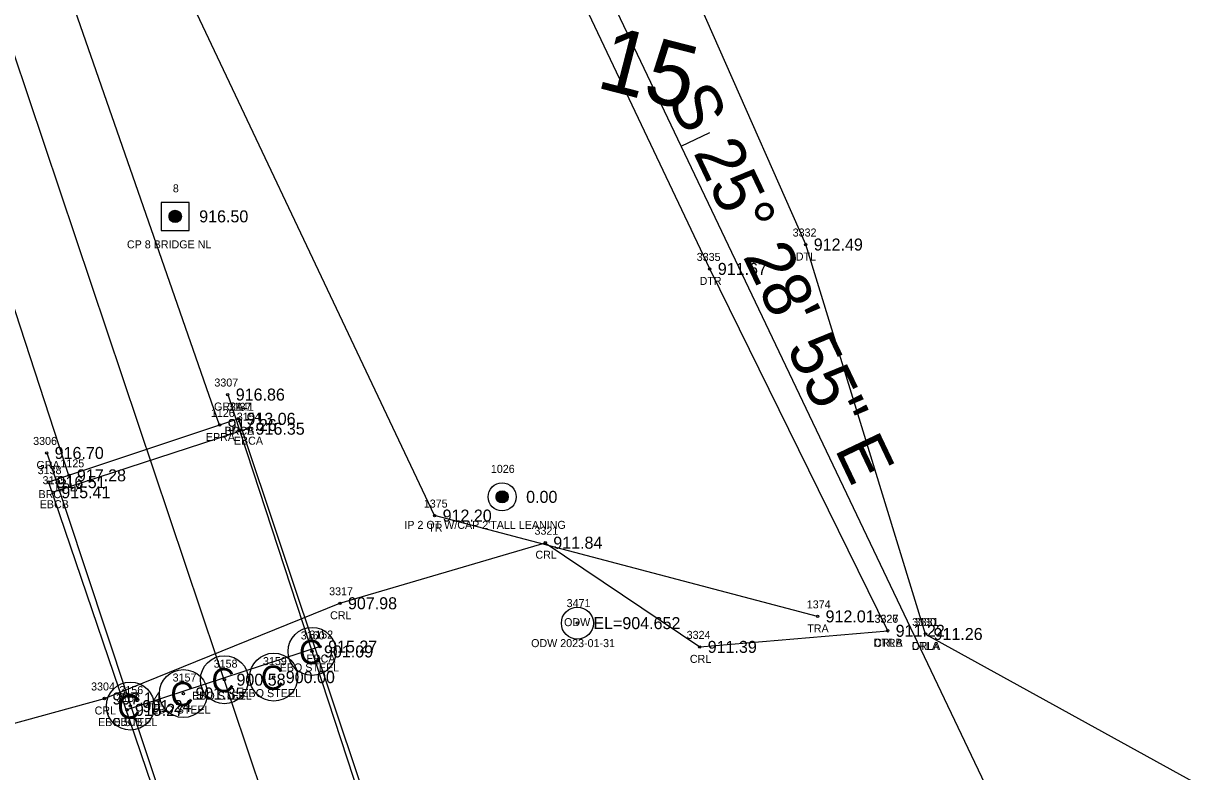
# Model space of a CAD drawing. Extents: x 1528109 to 1531398, y 1157799 to 1162548.
# Drawn here: x 1529613.7 to 1529759.7, y 1160294.1 to 1160387.6 of the extents above; entities that cross this region are included whole.
import ezdxf

# ---------------------------------------------------------------- set-up
doc = ezdxf.new("R2010")
doc.units = 0
for name, color, linetype in [('RD_EX_Bridge', 7, 'Continuous'), ('RD_EX_Bridge_txCode', 7, 'Continuous'), ('RD_EX_DV_Prop_txCode', 7, 'Continuous'), ('RD_EX_DV_PropPin', 7, 'Continuous'), ('RD_EX_GuardRail', 7, 'Continuous'), ('RD_EX_GuardRail_txCode', 7, 'Continuous'), ('RD_EX_H2O', 7, 'Continuous'), ('RD_EX_H2O_txCode', 7, 'Continuous'), ('RD_EX_Road', 7, 'Continuous'), ('RD_EX_Road_txCode', 7, 'Continuous'), ('RD_EX_TX_Bridge_ELEV', 7, 'Continuous'), ('RD_EX_TX_DV_Prop_ELEV', 7, 'Continuous'), ('RD_EX_TX_GuardRail_ELEV', 7, 'Continuous'), ('RD_EX_TX_H2O_ELEV', 7, 'Continuous'), ('RD_EX_TX_Road_ELEV', 7, 'Continuous'), ('RD_EX_TX_VEG_ELEV', 7, 'Continuous'), ('RD_EX_VEG', 7, 'Continuous'), ('RD_EX_VEG_txCode', 7, 'Continuous'), ('RD_HC_Cl', 7, 'Continuous'), ('RD_HC_Data', 7, 'Continuous'), ('RD_HC_Data_Tic', 7, 'Continuous'), ('RD_HC_Survey', 7, 'Continuous'), ('RD_HC_Survey_ELEV', 7, 'Continuous'), ('RD_HC_Survey_txCode', 7, 'Continuous'), ('RD_HC_TX_Sta50', 7, 'Continuous'), ('RD_SMD_Locator', 7, 'Continuous')]:
    doc.layers.add(name, color=color, linetype=linetype)

msp = doc.modelspace()

# ---------------------------------------------------------------- linework, layer by layer
at = {"layer": 'RD_EX_Bridge'}
for p, q in [((1529641.69, 1160336.95), (1529617.41, 1160329.01)), ((1529650.75, 1160309.72), (1529626.61, 1160301.81))]:
    msp.add_line(p, q, dxfattribs=at)
msp.add_lwpolyline([(1529640.55, 1160338.19), (1529616.81, 1160330.27), (1529655.43, 1160216.77), (1529678.49, 1160224.61), (1529640.55, 1160338.19)], dxfattribs=at)
for centre in [(1529649.74, 1160309.11), (1529638.8, 1160305.58), (1529644.96, 1160305.9), (1529633.67, 1160303.85), (1529627.04, 1160302.28)]:
    msp.add_circle(centre, 3, dxfattribs=at)
at = {"layer": 'RD_EX_DV_PropPin'}
for p, q in [((1529672.77, 1160328.23), (1529672.77, 1160328.62)), ((1529672.8, 1160328.13), (1529672.8, 1160328.73)), ((1529672.84, 1160328.06), (1529672.84, 1160328.8)), ((1529672.87, 1160328), (1529672.87, 1160328.85)), ((1529672.91, 1160327.95), (1529672.91, 1160328.9)), ((1529672.94, 1160327.91), (1529672.94, 1160328.94)), ((1529672.98, 1160327.88), (1529672.98, 1160328.98)), ((1529673.01, 1160327.85), (1529673.01, 1160329.01)), ((1529673.05, 1160327.82), (1529673.05, 1160329.04)), ((1529673.08, 1160327.79), (1529673.08, 1160329.06)), ((1529673.12, 1160327.77), (1529673.12, 1160329.08)), ((1529673.15, 1160327.75), (1529673.15, 1160329.1)), ((1529673.19, 1160327.74), (1529673.19, 1160329.12)), ((1529673.22, 1160327.72), (1529673.22, 1160329.14)), ((1529673.26, 1160327.71), (1529673.26, 1160329.15)), ((1529673.29, 1160327.7), (1529673.29, 1160329.16)), ((1529673.33, 1160327.69), (1529673.33, 1160329.17)), ((1529673.36, 1160327.68), (1529673.36, 1160329.18)), ((1529673.4, 1160327.67), (1529673.4, 1160329.18)), ((1529673.43, 1160327.67), (1529673.43, 1160329.19)), ((1529673.47, 1160327.67), (1529673.47, 1160329.19)), ((1529673.5, 1160327.67), (1529673.5, 1160329.19)), ((1529673.54, 1160327.67), (1529673.54, 1160329.19)), ((1529673.57, 1160327.67), (1529673.57, 1160329.19)), ((1529673.61, 1160327.67), (1529673.61, 1160329.18)), ((1529673.64, 1160327.68), (1529673.64, 1160329.18)), ((1529673.68, 1160327.69), (1529673.68, 1160329.17)), ((1529673.71, 1160327.7), (1529673.71, 1160329.16)), ((1529673.75, 1160327.71), (1529673.75, 1160329.15)), ((1529673.78, 1160327.72), (1529673.78, 1160329.14)), ((1529673.82, 1160327.74), (1529673.82, 1160329.12)), ((1529673.85, 1160327.75), (1529673.85, 1160329.1)), ((1529673.89, 1160327.77), (1529673.89, 1160329.08)), ((1529673.92, 1160327.79), (1529673.92, 1160329.06)), ((1529673.96, 1160327.82), (1529673.96, 1160329.04)), ((1529673.99, 1160327.85), (1529673.99, 1160329.01)), ((1529674.03, 1160327.88), (1529674.03, 1160328.98)), ((1529674.06, 1160327.91), (1529674.06, 1160328.94)), ((1529674.1, 1160327.95), (1529674.1, 1160328.9)), ((1529674.13, 1160328), (1529674.13, 1160328.85)), ((1529674.17, 1160328.06), (1529674.17, 1160328.8)), ((1529674.2, 1160328.13), (1529674.2, 1160328.73)), ((1529674.24, 1160328.23), (1529674.24, 1160328.62))]:
    msp.add_line(p, q, dxfattribs=at)
for radius in [1.75, 0.761]:
    msp.add_circle((1529673.5, 1160328.43), radius, dxfattribs=at)
at = {"layer": 'RD_EX_GuardRail'}
for points in [[(1529639.21, 1160341.22), (1529658.79, 1160281.43), (1529679.51, 1160220.29)], [(1529616.58, 1160333.92), (1529636.5, 1160273.84), (1529656.54, 1160212.79)]]:
    msp.add_lwpolyline(points, dxfattribs=at)
at = {"layer": 'RD_EX_H2O'}
for points in [[(1529721.68, 1160311.69), (1529699.45, 1160356.92), (1529667.22, 1160424.93), (1529635.88, 1160475.03)], [(1529212.56, 1160420.69), (1529289.94, 1160452.31), (1529331.04, 1160457.54), (1529371.94, 1160452.7), (1529411.5, 1160420.02), (1529456.02, 1160392.77), (1529494.52, 1160341.06), (1529560.21, 1160297.91), (1529595.85, 1160295.56), (1529623.8, 1160303.23), (1529653.23, 1160315.13), (1529678.89, 1160322.7), (1529698.19, 1160309.68), (1529721.68, 1160311.69)], [(1529726.41, 1160311.29), (1529711.44, 1160359.97), (1529679.1, 1160433.25), (1529696.96, 1160440.59)], [(1529726.41, 1160311.29), (1529822.85, 1160258.09), (1529888.47, 1160243.37), (1529986.9, 1160229.42), (1530037.08, 1160228.61), (1530104.23, 1160168.21), (1530147.93, 1160110.54), (1530175.68, 1160088.08)]]:
    msp.add_lwpolyline(points, dxfattribs=at)
for radius in [2, 0.15]:
    msp.add_circle((1529682.9, 1160312.65), radius, dxfattribs=at)
at = {"layer": 'RD_EX_Road'}
for points in [[(1529638.19, 1160337.41), (1529618.52, 1160393.92), (1529601.47, 1160445.09), (1529582.35, 1160502.18), (1529566.78, 1160548.91), (1529548.34, 1160605.67), (1529547.84, 1160613.14)], [(1529619.36, 1160331.12), (1529600.6, 1160388.5), (1529583.59, 1160439.6), (1529564.67, 1160495.86), (1529548.92, 1160543.15), (1529530.19, 1160599.08), (1529525.69, 1160605.63)]]:
    msp.add_lwpolyline(points, dxfattribs=at)
at = {"layer": 'RD_EX_VEG'}
msp.add_lwpolyline([(1529712.92, 1160313.49), (1529665.06, 1160326.09), (1529626.42, 1160407.72), (1529580.03, 1160531.48), (1529510.74, 1160760.21), (1529455.97, 1160902.21), (1529420.7, 1161006.64), (1529376.36, 1161143.49), (1529336.53, 1161275.85), (1529306.04, 1161391.66)], dxfattribs=at)
at = {"layer": 'RD_HC_Cl'}
for p, q in [((1529913.5, 1159487.74), (1529527.85, 1160635.77)), ((1529658.39, 1160450.88), (1529753.92, 1160250.44))]:
    msp.add_line(p, q, dxfattribs=at)
at = {"layer": 'RD_HC_Data_Tic'}
msp.add_line((1529695.86, 1160372.26), (1529699.47, 1160373.98), dxfattribs=at)
at = {"layer": 'RD_HC_Survey'}
for p, q in [((1529631.89, 1160363.31), (1529631.89, 1160363.67)), ((1529631.91, 1160363.23), (1529631.91, 1160363.75)), ((1529631.94, 1160363.17), (1529631.94, 1160363.81)), ((1529631.96, 1160363.12), (1529631.96, 1160363.86)), ((1529631.99, 1160363.08), (1529631.99, 1160363.9)), ((1529632.01, 1160363.04), (1529632.01, 1160363.94)), ((1529632.04, 1160363.01), (1529632.04, 1160363.97)), ((1529632.06, 1160362.98), (1529632.06, 1160364)), ((1529632.09, 1160362.95), (1529632.09, 1160364.03)), ((1529632.11, 1160362.93), (1529632.11, 1160364.05)), ((1529632.13, 1160362.9), (1529632.13, 1160364.07)), ((1529632.16, 1160362.88), (1529632.16, 1160364.09)), ((1529632.18, 1160362.87), (1529632.18, 1160364.11)), ((1529632.21, 1160362.85), (1529632.21, 1160364.13)), ((1529632.23, 1160362.83), (1529632.23, 1160364.14)), ((1529632.26, 1160362.82), (1529632.26, 1160364.16)), ((1529632.28, 1160362.8), (1529632.28, 1160364.17)), ((1529632.31, 1160362.79), (1529632.31, 1160364.18)), ((1529632.33, 1160362.78), (1529632.33, 1160364.2)), ((1529632.36, 1160362.77), (1529632.36, 1160364.21)), ((1529632.38, 1160362.76), (1529632.38, 1160364.21)), ((1529632.41, 1160362.75), (1529632.41, 1160364.22)), ((1529632.43, 1160362.75), (1529632.43, 1160364.23)), ((1529632.46, 1160362.74), (1529632.46, 1160364.24)), ((1529632.48, 1160362.73), (1529632.48, 1160364.24)), ((1529632.51, 1160362.73), (1529632.51, 1160364.25)), ((1529632.53, 1160362.73), (1529632.53, 1160364.25)), ((1529632.56, 1160362.72), (1529632.56, 1160364.25)), ((1529632.58, 1160362.72), (1529632.58, 1160364.26)), ((1529632.61, 1160362.72), (1529632.61, 1160364.26)), ((1529632.63, 1160362.72), (1529632.63, 1160364.26)), ((1529632.65, 1160362.72), (1529632.65, 1160364.26)), ((1529632.68, 1160362.72), (1529632.68, 1160364.26)), ((1529632.7, 1160362.72), (1529632.7, 1160364.25)), ((1529632.73, 1160362.72), (1529632.73, 1160364.25)), ((1529632.75, 1160362.73), (1529632.75, 1160364.25)), ((1529632.78, 1160362.73), (1529632.78, 1160364.24)), ((1529632.8, 1160362.74), (1529632.8, 1160364.24)), ((1529632.83, 1160362.74), (1529632.83, 1160364.23)), ((1529632.85, 1160362.75), (1529632.85, 1160364.23)), ((1529632.88, 1160362.76), (1529632.88, 1160364.22)), ((1529632.9, 1160362.77), (1529632.9, 1160364.21)), ((1529632.93, 1160362.78), (1529632.93, 1160364.2)), ((1529632.95, 1160362.79), (1529632.95, 1160364.19)), ((1529632.98, 1160362.8), (1529632.98, 1160364.18)), ((1529633, 1160362.81), (1529633, 1160364.17)), ((1529633.03, 1160362.83), (1529633.03, 1160364.15)), ((1529633.05, 1160362.84), (1529633.05, 1160364.14)), ((1529633.08, 1160362.86), (1529633.08, 1160364.12)), ((1529633.1, 1160362.87), (1529633.1, 1160364.1)), ((1529633.12, 1160362.89), (1529633.12, 1160364.08)), ((1529633.15, 1160362.92), (1529633.15, 1160364.06)), ((1529633.17, 1160362.94), (1529633.17, 1160364.04)), ((1529633.2, 1160362.96), (1529633.2, 1160364.01)), ((1529633.22, 1160362.99), (1529633.22, 1160363.98)), ((1529633.25, 1160363.02), (1529633.25, 1160363.95)), ((1529633.27, 1160363.06), (1529633.27, 1160363.92)), ((1529633.3, 1160363.1), (1529633.3, 1160363.88)), ((1529633.32, 1160363.14), (1529633.32, 1160363.83)), ((1529633.35, 1160363.2), (1529633.35, 1160363.78)), ((1529633.37, 1160363.27), (1529633.37, 1160363.71)), ((1529633.4, 1160363.38), (1529633.4, 1160363.6))]:
    msp.add_line(p, q, dxfattribs=at)
msp.add_lwpolyline([(1529634.39, 1160365.24), (1529630.89, 1160365.24), (1529630.89, 1160361.74), (1529634.39, 1160361.74)], close=True, dxfattribs=at)
msp.add_circle((1529632.64, 1160363.49), 0.769, dxfattribs=at)
at = {"layer": 'RD_SMD_Locator'}
for centre in [(1529632.64, 1160363.49), (1529711.44, 1160359.97), (1529699.45, 1160356.92), (1529639.21, 1160341.22), (1529640.55, 1160338.19), (1529640.55, 1160338.19), (1529638.19, 1160337.41), (1529641.69, 1160336.95), (1529616.58, 1160333.92), (1529619.36, 1160331.12), (1529616.81, 1160330.27), (1529617.41, 1160329.01), (1529673.5, 1160328.43), (1529665.06, 1160326.09), (1529678.89, 1160322.7), (1529653.23, 1160315.13), (1529712.92, 1160313.49), (1529721.68, 1160311.69), (1529721.68, 1160311.69), (1529726.41, 1160311.29), (1529726.41, 1160311.29), (1529649.74, 1160309.11), (1529650.75, 1160309.72), (1529698.19, 1160309.68), (1529638.8, 1160305.58), (1529644.96, 1160305.9), (1529623.8, 1160303.23), (1529633.67, 1160303.85), (1529626.61, 1160301.81), (1529627.04, 1160302.28)]:
    msp.add_circle(centre, 0.15, dxfattribs=at)

# ---------------------------------------------------------------- texts
at = {"layer": 'RD_EX_Bridge'}
for p in [(1529648.11, 1160307.55), (1529637.17, 1160304.02), (1529643.33, 1160304.34), (1529632.04, 1160302.29), (1529625.41, 1160300.72)]:
    msp.add_text('C', height=3, dxfattribs=at).set_placement(p)
at = {"layer": 'RD_EX_Bridge_txCode'}
for s, p in [('3137', (1529639.2, 1160339.19)), ('3141', (1529639.48, 1160339.19)), ('3154', (1529640.34, 1160337.95)), ('BRCA', (1529638.8, 1160336.19)), ('BRCB', (1529638.82, 1160336.19)), ('EBCA', (1529639.97, 1160334.95)), ('3138', (1529615.46, 1160331.27)), ('3155', (1529616.07, 1160330.01)), ('BRC', (1529615.56, 1160328.27)), ('EBCB', (1529615.71, 1160327.01)), ('3160', (1529648.33, 1160310.61)), ('3152', (1529649.4, 1160310.72)), ('3158', (1529637.45, 1160307.08)), ('3159', (1529643.61, 1160307.4)), ('EBCA', (1529649.03, 1160307.72)), ('3157', (1529632.32, 1160305.35)), ('EBO STEEL', (1529645.7, 1160306.61)), ('3156', (1529625.67, 1160303.78)), ('3153', (1529625.27, 1160302.81)), ('EBO STEEL', (1529634.76, 1160303.08)), ('EBO STEEL', (1529640.92, 1160303.4)), ('EBO STEEL', (1529629.63, 1160301.35)), ('EBO STEEL', (1529623, 1160299.78)), ('EBCB', (1529624.91, 1160299.81))]:
    msp.add_text(s, height=1, dxfattribs=at).set_placement(p)
at = {"layer": 'RD_EX_DV_Prop_txCode'}
for s, p in [('1026', (1529672.09, 1160331.43)), ("IP 2 OT W/CAP 2'TALL LEANING", (1529661.28, 1160324.43))]:
    msp.add_text(s, height=1, dxfattribs=at).set_placement(p)
at = {"layer": 'RD_EX_GuardRail_txCode'}
for s, p in [('3307', (1529637.54, 1160342.22)), ('GR2A', (1529637.49, 1160339.22)), ('3306', (1529614.89, 1160334.92)), ('GRA', (1529615.31, 1160331.92))]:
    msp.add_text(s, height=1, dxfattribs=at).set_placement(p)
at = {"layer": 'RD_EX_H2O'}
msp.add_text('ODW', height=1, dxfattribs=at).set_placement((1529681.24, 1160312.27))
at = {"layer": 'RD_EX_H2O_txCode'}
for s, p in [('3332', (1529709.81, 1160360.97)), ('3335', (1529697.82, 1160357.92)), ('DTL', (1529710.2, 1160357.97)), ('DTR', (1529698.18, 1160354.92)), ('3321', (1529677.54, 1160323.7)), ('CRL', (1529677.66, 1160320.7)), ('3317', (1529651.88, 1160316.13)), ('3471', (1529681.56, 1160314.65)), ('CRL', (1529652, 1160313.13)), ('3326', (1529720.02, 1160312.69)), ('3327', (1529720.05, 1160312.69)), ('3330', (1529724.74, 1160312.29)), ('3331', (1529725.06, 1160312.29)), ('ODW 2023-01-31', (1529677.12, 1160309.65)), ('3324', (1529696.56, 1160310.68)), ('DTRA', (1529719.92, 1160309.69)), ('CRLB', (1529719.98, 1160309.69)), ('CRLA', (1529724.69, 1160309.29)), ('DTLA', (1529724.68, 1160309.29)), ('CRL', (1529696.96, 1160307.68)), ('3304', (1529622.13, 1160304.23)), ('CRL', (1529622.57, 1160301.23))]:
    msp.add_text(s, height=1, dxfattribs=at).set_placement(p)
at = {"layer": 'RD_EX_Road_txCode'}
for s, p in [('1126', (1529637.1, 1160338.41)), ('EPRA', (1529636.47, 1160335.41)), ('1125', (1529618.3, 1160332.12)), ('EPLA', (1529617.67, 1160329.12))]:
    msp.add_text(s, height=1, dxfattribs=at).set_placement(p)
at = {"layer": 'RD_EX_TX_Bridge_ELEV'}
for s, p in [('913.06', (1529641.55, 1160337.44)), ('913.06', (1529641.55, 1160337.44)), ('916.35', (1529642.69, 1160336.2)), ('916.51', (1529617.81, 1160329.52)), ('915.41', (1529618.41, 1160328.26)), ('901.09', (1529651.24, 1160308.36)), ('915.27', (1529651.75, 1160308.97)), ('900.58', (1529640.3, 1160304.83)), ('900.00', (1529646.46, 1160305.15)), ('901.35', (1529635.17, 1160303.1)), ('915.27', (1529627.61, 1160301.06)), ('901.24', (1529628.54, 1160301.53))]:
    msp.add_text(s, height=1.5, dxfattribs=at).set_placement(p)
at = {"layer": 'RD_EX_TX_DV_Prop_ELEV'}
msp.add_text('0.00', height=1.5, dxfattribs=at).set_placement((1529676.5, 1160327.68))
at = {"layer": 'RD_EX_TX_GuardRail_ELEV'}
for s, p in [('916.86', (1529640.21, 1160340.47)), ('916.70', (1529617.58, 1160333.17))]:
    msp.add_text(s, height=1.5, dxfattribs=at).set_placement(p)
at = {"layer": 'RD_EX_TX_H2O_ELEV'}
for s, p in [('912.49', (1529712.44, 1160359.22)), ('911.67', (1529700.45, 1160356.17)), ('911.84', (1529679.89, 1160321.95)), ('907.98', (1529654.23, 1160314.38)), ('EL=904.652', (1529684.9, 1160311.9)), ('911.22', (1529722.68, 1160310.94)), ('911.22', (1529722.68, 1160310.94)), ('911.26', (1529727.41, 1160310.54)), ('911.26', (1529727.41, 1160310.54)), ('911.39', (1529699.19, 1160308.93)), ('907.14', (1529624.8, 1160302.48))]:
    msp.add_text(s, height=1.5, dxfattribs=at).set_placement(p)
at = {"layer": 'RD_EX_TX_Road_ELEV'}
for s, p in [('917.26', (1529639.19, 1160336.66)), ('917.28', (1529620.36, 1160330.37))]:
    msp.add_text(s, height=1.5, dxfattribs=at).set_placement(p)
at = {"layer": 'RD_EX_TX_VEG_ELEV'}
for s, p in [('912.20', (1529666.06, 1160325.34)), ('912.01', (1529713.92, 1160312.74))]:
    msp.add_text(s, height=1.5, dxfattribs=at).set_placement(p)
at = {"layer": 'RD_EX_VEG_txCode'}
for s, p in [('1375', (1529663.71, 1160327.09)), ('TR', (1529664.26, 1160324.09)), ('1374', (1529711.57, 1160314.49)), ('TRA', (1529711.63, 1160311.49))]:
    msp.add_text(s, height=1, dxfattribs=at).set_placement(p)
at = {"layer": 'RD_HC_Data'}
msp.add_text('S 25%%d 28\' 55" E', height=6, rotation=295.4821, dxfattribs=at).set_placement((1529694.08, 1160378.32))
at = {"layer": 'RD_HC_Survey_ELEV'}
msp.add_text('916.50', height=1.5, dxfattribs=at).set_placement((1529635.64, 1160362.74))
at = {"layer": 'RD_HC_Survey_txCode'}
for s, p in [('8', (1529632.35, 1160366.49)), ('CP 8 BRIDGE NL', (1529626.61, 1160359.49))]:
    msp.add_text(s, height=1, dxfattribs=at).set_placement(p)
at = {"layer": 'RD_HC_TX_Sta50'}
msp.add_text('15', height=8, rotation=345.5786, dxfattribs=at).set_placement((1529685.08, 1160379.65))

doc.saveas('drawing.dxf')
